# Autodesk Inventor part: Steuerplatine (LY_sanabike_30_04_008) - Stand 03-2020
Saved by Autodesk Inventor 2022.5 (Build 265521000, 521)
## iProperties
Created: 2024-12
Part Number: Steuerplatine (LY_sanabike_30_04_008) - Stand 03-2020
Material: Generic
Document SubType Name: Modeling
Designer: AdminForWorker
Density: 1 g/cm^3
Appearance: Default
Title: Steuerplatine (LY_sanabike_30_04_008) - Stand 03-2020
Author: AdminForWorker
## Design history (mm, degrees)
feature "Body1"
feature "Body2"
feature "Body3"
feature "Body4"
feature "Body5"
feature "Body6"
feature "Body7"
feature "Body8"
feature "Body9"
feature "Body10"
feature "Body11"
feature "Body12"
feature "Body13"
feature "Body14"
feature "Body15"
feature "Body16"
feature "Body17"
feature "Body18"
feature "Body19"
feature "Body20"
feature "Body21"
feature "Body22"
feature "Body23"
feature "Body24"
feature "Body25"
feature "Body26"
feature "Body27"
feature "Body28"
feature "Body29"
feature "Body30"
feature "Body31"
feature "Body32"
feature "Body33"
feature "Body34"
feature "Body35"
feature "Body36"
feature "Body37"
feature "Body38"
feature "Body39"
feature "Body40"
feature "Body41"
feature "Body42"
feature "Body43"
feature "Body44"
feature "Body45"
feature "Body46"
feature "Body47"
feature "Body48"
feature "Body49"
feature "Body50"
feature "Body51"
feature "Body52"
feature "Body53"
feature "Body54"
feature "Body55"
feature "Body56"
feature "Body57"
feature "Body58"
feature "Body59"
feature "Body60"
feature "Body61"
feature "Body62"
feature "Body63"
feature "Body64"
feature "Body65"
feature "Body66"
feature "Body67"
feature "Body68"
feature "Body69"
feature "Body70"
feature "Body71"
feature "Body72"
feature "Body73"
feature "Body74"
feature "Body75"
feature "Body76"
feature "Body77"
feature "Body78"
feature "Body79"
feature "Body80"
feature "Body81"
feature "Body82"
feature "Body83"
feature "Body84"
feature "Body85"
feature "Body86"
feature "Body87"
feature "Body88"
feature "Body89"
feature "Body90"
feature "Body91"
feature "Body92"
feature "Body93"
feature "Body94"
feature "Body95"
feature "Body96"
feature "Body97"
feature "Body98"
feature "Body99"
feature "Body100"
feature "Body101"
feature "Body102"
feature "Body103"
feature "Body104"
feature "Body105"
feature "Body106"
feature "Body107"
feature "Body108"
feature "Body109"
feature "Body110"
feature "Body111"
feature "Body112"
feature "Body113"
feature "Body114"
feature "Body115"
feature "Body116"
feature "Body117"
feature "Body118"
feature "Body119"
feature "Body120"
feature "Body121"
feature "Body122"
feature "Body123"
feature "Body124"
feature "Body125"
feature "Body126"
feature "Body127"
feature "Body128"
feature "Body129"
feature "Body130"
feature "Body131"
feature "Body132"
feature "Body133"
feature "Body134"
feature "Body135"
feature "Body136"
feature "Body137"
feature "Body138"
feature "Body139"
feature "Body140"
feature "Body141"
feature "Body142"
feature "Body143"
feature "Body144"
feature "Body145"
feature "Body146"
feature "Body147"
feature "Body148"
feature "Body149"
feature "Body150"
feature "Body151"
feature "Body152"
feature "Body153"
feature "Body154"
feature "Body155"
feature "Body156"
feature "Body157"
feature "Body158"
feature "Body159"
feature "Body160"
feature "Body161"
feature "Body162"
feature "Body163"
feature "Body164"
feature "Body165"
feature "Body166"
feature "Body167"
feature "Body168"
feature "Body169"
feature "Body170"
feature "Body171"
feature "Body172"
feature "Body173"
feature "Body174"
feature "Body175"
feature "Body176"
feature "Body177"
body "Solid1"
body "Solid2"
body "Solid3"
body "Solid4"
body "Solid5"
body "Solid6"
body "Solid7"
body "Solid8"
body "Solid9"
body "Solid10"
body "Solid11"
body "Solid12"
body "Solid13"
body "Solid14"
body "Solid15"
body "Solid16"
body "Solid17"
body "Solid18"
body "Solid19"
body "Solid20"
body "Solid21"
body "Solid22"
body "Solid23"
body "Solid24"
body "Solid25"
body "Solid26"
body "Solid27"
body "Solid28"
body "Solid29"
body "Solid30"
body "Solid31"
body "Solid32"
body "Solid33"
body "Solid34"
body "Solid35"
body "Solid36"
body "Solid37"
body "Solid38"
body "Solid39"
body "Solid40"
body "Solid41"
body "Solid42"
body "Solid43"
body "Solid44"
body "Solid45"
body "Solid46"
body "Solid47"
body "Solid48"
body "Solid49"
body "Solid50"
body "Solid51"
body "Solid52"
body "Solid53"
body "Solid54"
body "Solid55"
body "Solid56"
body "Solid57"
body "Solid58"
body "Solid59"
body "Solid60"
body "Solid61"
body "Solid62"
body "Solid63"
body "Solid64"
body "Solid65"
body "Solid66"
body "Solid67"
body "Solid68"
body "Solid69"
body "Solid70"
body "Solid71"
body "Solid72"
body "Solid73"
body "Solid74"
body "Solid75"
body "Solid76"
body "Solid77"
body "Solid78"
body "Solid79"
body "Solid80"
body "Solid81"
body "Solid82"
body "Solid83"
body "Solid84"
body "Solid85"
body "Solid86"
body "Solid87"
body "Solid88"
body "Solid89"
body "Solid90"
body "Solid91"
body "Solid92"
body "Solid93"
body "Solid94"
body "Solid95"
body "Solid96"
body "Solid97"
body "Solid98"
body "Solid99"
body "Solid100"
body "Solid101"
body "Solid102"
body "Solid103"
body "Solid104"
body "Solid105"
body "Solid106"
body "Solid107"
body "Solid108"
body "Solid109"
body "Solid110"
body "Solid111"
body "Solid112"
body "Solid113"
body "Solid114"
body "Solid115"
body "Solid116"
body "Solid117"
body "Solid118"
body "Solid119"
body "Solid120"
body "Solid121"
body "Solid122"
body "Solid123"
body "Solid124"
body "Solid125"
body "Solid126"
body "Solid127"
body "Solid128"
body "Solid129"
body "Solid130"
body "Solid131"
body "Solid132"
body "Solid133"
body "Solid134"
body "Solid135"
body "Solid136"
body "Solid137"
body "Solid138"
body "Solid139"
body "Solid140"
body "Solid141"
body "Solid142"
body "Solid143"
body "Solid144"
body "Solid145"
body "Solid146"
body "Solid147"
body "Solid148"
body "Solid149"
body "Solid150"
body "Solid151"
body "Solid152"
body "Solid153"
body "Solid154"
body "Solid155"
body "Solid156"
body "Solid157"
body "Solid158"
body "Solid159"
body "Solid160"
body "Solid161"
body "Solid162"
body "Solid163"
body "Solid164"
body "Solid165"
body "Solid166"
body "Solid167"
body "Solid168"
body "Solid169"
body "Solid170"
body "Solid171"
body "Solid172"
body "Solid173"
body "Solid174"
body "Solid175"
body "Solid176"
body "Solid177"
